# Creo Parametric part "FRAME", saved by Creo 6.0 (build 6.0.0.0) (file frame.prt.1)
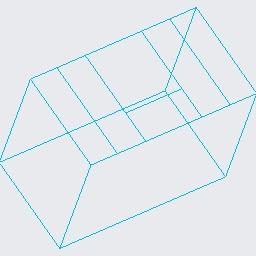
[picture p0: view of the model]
Units: millimeter Newton Second (mmNs); MM, TONNE, SECS

Created from: MMNS_PART_SOLID.PRT

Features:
  1. datum plane "RIGHT"
  2. datum plane "TOP"
  3. datum plane "FRONT"
  4. coordinate system
  5. sketch "Sketch 1"
  6. datum plane "DTM1"
  7. sketch "Sketch 2"
  8. mirror "Mirror 1"
  9. sketch "Sketch 2 (2)"
  10. datum plane "DTM2"
  11. mirror "Mirror 2"
  12. mirror "Mirror 3"
  13. datum plane "DTM3"
  14. sketch "Sketch 3"
  15. mirror "Mirror 4"
  16. sketch "Sketch 1 (2)"
  17. sketch "Sketch 4"
  18. sketch "Sketch 5"
  19. mirror "Mirror 5"
  20. sketch "Sketch 5 (2)"

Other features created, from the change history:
  sketch "Sketch 1"
  datum plane "DTM1"

Other named items: FRONT_1, FRONT_2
